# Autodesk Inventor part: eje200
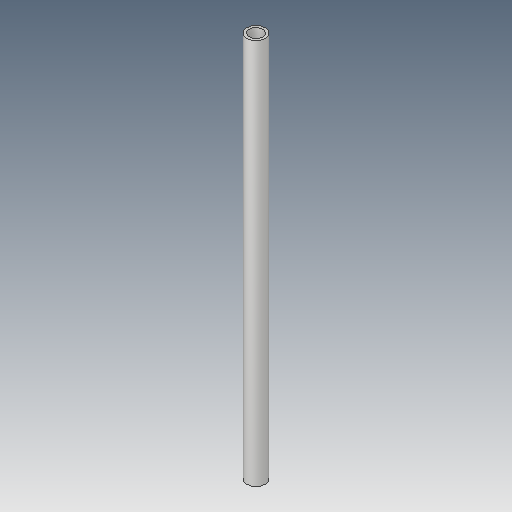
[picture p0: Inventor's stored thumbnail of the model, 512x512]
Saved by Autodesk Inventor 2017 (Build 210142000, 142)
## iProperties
Created: 2018-08
Part Number: eje200
Material: Aluminum
Document SubType Name: Modeling
Designer: JK
Density: 2.7 g/cm^3
Appearance: Satin
Author: JK
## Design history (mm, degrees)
sketch "Sketch1"
  geometry: C1 r 4.8 at (0, 0); C2 r 3.5 at (0, 0); 1 further point
  constraints: 2 centre point, 2 coincident
  dimensions: "d0" = 9.6 diameter of C1; "d1" = 7 diameter of C2
extrude "Extrusion1" new body sketch "Sketch1" distance "d2" = 200; taper "d3" = 0 deg
body "Solid1"
